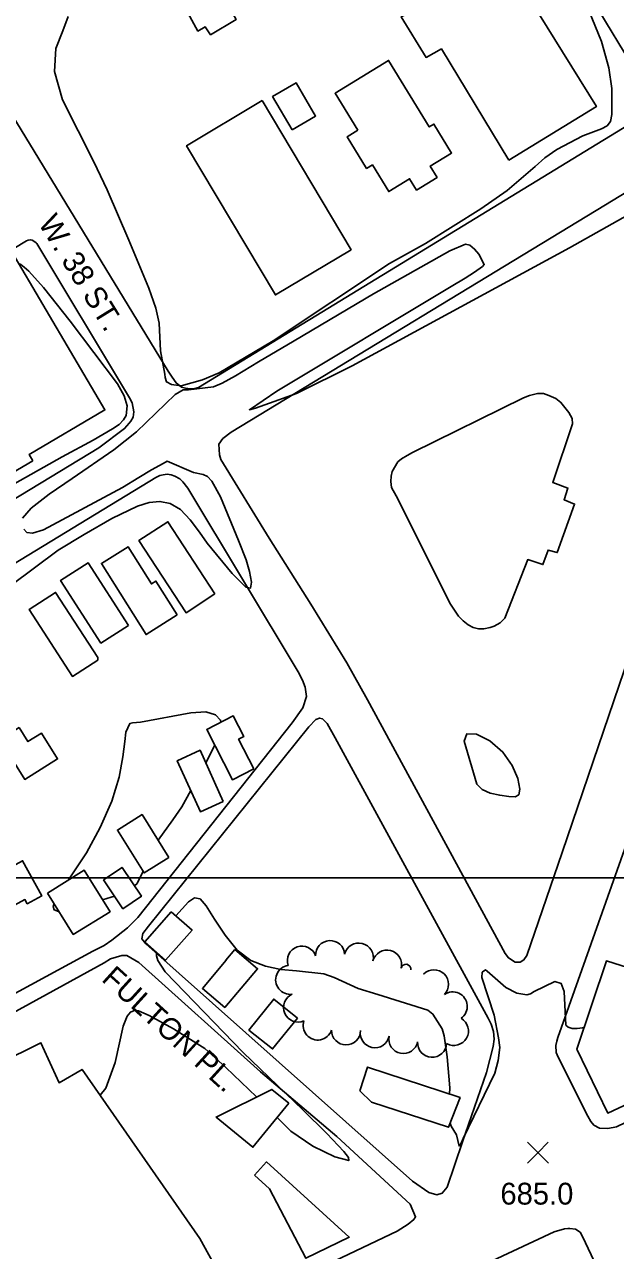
# Model space of a CAD drawing. Extents: x 79600 to 91800, y 75600 to 84400.
# Drawn here: x 81024 to 81430, y 82744 to 83587 of the extents above; entities that cross this region are included whole.
import ezdxf

# ---------------------------------------------------------------- set-up
doc = ezdxf.new("R2010")
doc.units = 0
for name, color, linetype in [('084-085$0$BLDG', 7, 'Continuous'), ('084-085$0$GRID', 7, 'Continuous'), ('084-085$0$INTER', 7, 'Continuous'), ('084-085$0$ROAD', 7, 'Continuous'), ('084-085$0$ROAD-NAME', 7, 'Continuous'), ('084-085$0$SPOTMARK', 7, 'Continuous'), ('084-085$0$SPOTS', 7, 'Continuous'), ('084-085$0$TREES', 7, 'Continuous')]:
    doc.layers.add(name, color=color, linetype=linetype)

# ---------------------------------------------------------------- blocks, each defined once
blk = doc.blocks.new('084-085$0$SPOTX')
at = {"layer": '084-085$0$SPOTMARK'}
for p, q in [((-0.37, 0.358), (0.351, -0.358)), ((-0.012, 0), (-0.37, -0.358)), ((-0.012, 0), (0.347, 0.358))]:
    blk.add_line(p, q, dxfattribs=at)

msp = doc.modelspace()

# ---------------------------------------------------------------- linework, layer by layer
at = {"layer": '084-085$0$BLDG'}
for points in [[(81106.06, 83643.89), (81126.19, 83656.27), (81134.29, 83642.84), (81138.56, 83645.29), (81167.76, 83598.92), (81165.47, 83597.55), (81169.6, 83590.22), (81151.9, 83579.68), (81148.24, 83585.02), (81143.2, 83582.26), (81127.91, 83610.18), (81115.1, 83602.08), (81103.33, 83624.65), (81114.16, 83630.31)], [(81357.1, 83493.34), (81310.63, 83569.91), (81300.11, 83564.1), (81282.99, 83592.01), (81292.9, 83597.06), (81280.98, 83618.41), (81295.78, 83625.45), (81295.16, 83627.43), (81294.7, 83631.09), (81294.55, 83634.75), (81295.15, 83638.72), (81296.98, 83642.85), (81299.12, 83645.44), (81302.78, 83648.19), (81305.52, 83649.72), (81307.66, 83650.33), (81311.17, 83650.64), (81314.68, 83650.65), (81316.2, 83650.65), (81317.88, 83650.65), (81326.89, 83646.08), (81329.03, 83642.57), (81343.06, 83649.91), (81417.2, 83530.33)], [(81253.1, 83514.02), (81245.85, 83509.57), (81259.23, 83487.73), (81263.23, 83490.18), (81274.44, 83471.89), (81288.79, 83480.68), (81293.54, 83472.93), (81307.73, 83481.63), (81302.98, 83489.38), (81317.66, 83498.38), (81305.49, 83518.23), (81302.33, 83516.29), (81274.32, 83562), (81237.52, 83539.44)], [(81208.07, 83514.24), (81224.16, 83523.72), (81210.67, 83546.63), (81194.58, 83537.15)], [(81187.46, 83534.45), (81248.55, 83431.89), (81196.45, 83400.86), (81135.36, 83503.42)], [(81029.59, 83286.81), (81027.11, 83291.02), (81079.2, 83321.69), (81015.17, 83430.43), (80919.56, 83374.13), (80927.91, 83359.94), (80918.99, 83354.69), (80977.15, 83255.93)], [(81400.77, 83312.07), (81387.22, 83271.92), (81397.61, 83267.96), (81395.02, 83260.03), (81402.2, 83256.98), (81390.32, 83223.7), (81384.06, 83225.37), (81380.41, 83215.45), (81370.03, 83218.8), (81354.35, 83178.64), (81351.15, 83175.28), (81347.03, 83172.99), (81344.28, 83172.07), (81339.86, 83171.3), (81336.19, 83171.3), (81332.38, 83172.21), (81329.02, 83173.89), (81325.51, 83176.63), (81322.45, 83179.99), (81316.95, 83188.07), (81279.49, 83262.66), (81276.28, 83268.31), (81275.97, 83272.43), (81276.12, 83276.09), (81276.88, 83279.45), (81280.69, 83286.01), (81283.28, 83288.15), (81287.09, 83290.45), (81290.75, 83292.43), (81367.18, 83330.05), (81371.3, 83331.58), (81376.64, 83332.96), (81380.91, 83332.96), (81384.57, 83331.75), (81389.31, 83329.61), (81392.82, 83326.87), (81398.17, 83320.01), (81400.46, 83315.89)], [(81154.93, 83195.25), (81122.55, 83244.87), (81102.65, 83231.88), (81135.02, 83182.26)], [(81128.96, 83180.75), (81114.28, 83204.06), (81111.26, 83202.16), (81095.17, 83227.71), (81076.87, 83216.19), (81107.62, 83167.32)], [(81095.38, 83173.58), (81067.64, 83216.62), (81048.77, 83204.46), (81076.51, 83161.42)], [(81074.33, 83149.7), (81074.33, 83151.58), (81045.38, 83196.3), (81027.13, 83184.49), (81056.94, 83138.45)], [(81181.55, 83074.93), (81171.14, 83095.35), (81174.69, 83097.16), (81167.45, 83111.35), (81149.32, 83102.11), (81166.98, 83067.49)], [(81020.31, 83103.28), (81026.31, 83093.73), (81035.61, 83099.57), (81046.73, 83081.84), (81024.15, 83067.67), (81007.03, 83094.94)], [(81160.64, 83052.57), (81144.75, 83087.69), (81129.04, 83080.58), (81144.92, 83045.46)], [(81123.24, 83014.03), (81104.76, 83043.51), (81087.84, 83032.9), (81106.32, 83003.42)], [(81003.87, 82993.5), (80994.52, 82988.42), (81002.68, 82973.42), (81024.21, 82985.12), (81025.82, 82982.16), (81035.78, 82987.57), (81022.65, 83011.73), (81000.51, 82999.69)], [(81039.8, 82989.58), (81065.04, 83005.26), (81082.76, 82976.76), (81057.52, 82961.07)], [(81078.29, 82998.59), (81091.59, 82978.76), (81104.38, 82987.34), (81091.09, 83007.17)], [(81124.9, 82976.66), (81106.64, 82955.92), (81120.95, 82943.32), (81139.21, 82964.06)], [(81168.56, 82950.76), (81162.41, 82943.51), (81162.65, 82943.31), (81146.27, 82923.97), (81161.69, 82910.91), (81184.21, 82937.51)], [(81494.44, 82870.8), (81425.03, 82838.22), (81403.77, 82882.16), (81424.17, 82942.92), (81468.28, 82928.92), (81471.8, 82918.7), (81453.04, 82909.83), (81448.63, 82894.87), (81450.77, 82889.83), (81466.79, 82895.95), (81465.41, 82900.83), (81478.07, 82906.34), (81480.82, 82902.38), (81502.03, 82911.71), (81508.45, 82899.65), (81506.01, 82898.28), (81515.8, 82875.4), (81498.26, 82866.22)], [(81211.58, 82903.6), (81195.32, 82916.61), (81178.3, 82895.35), (81194.56, 82882.34)], [(81254.54, 82853.63), (81259.87, 82869.96), (81323.53, 82848.96), (81315.61, 82828.5), (81262.64, 82845.85)], [(81205.74, 82845.04), (81181.08, 82814.8), (81155.66, 82835.53), (81194.02, 82854.6)], [(81182.02, 82795.57), (81192.46, 82786.11), (81217.41, 82738.52), (81247.31, 82753.05), (81190.26, 82804.68)]]:
    msp.add_lwpolyline(points, close=True, dxfattribs=at)
msp.add_lwpolyline([(81165.55, 82713.75), (81144.6, 82752.03), (81063.6, 82868.25), (81047.74, 82859.08), (81035.2, 82886.69), (80947.64, 82843.26), (80969.06, 82792.01), (80928.17, 82771.36), (80965.79, 82690.97)], dxfattribs=at)
at = {"layer": '084-085$0$GRID'}
msp.add_line((85000, 83000), (80000, 83000), dxfattribs=at)
at = {"layer": '084-085$0$INTER'}
msp.add_line((81148.61, 83079.17), (81154.84, 83091.29), dxfattribs=at)
for points in [[(81053.97, 83592.15), (81050.21, 83582.46), (81045.54, 83570.17), (81044.48, 83554.44), (81050.19, 83534.94), (81071.59, 83492.22), (81080.86, 83473.01), (81095.6, 83438.37), (81109.41, 83405.4), (81114.2, 83391.79), (81116.45, 83381.49), (81117.54, 83362.44), (81120.36, 83346.39), (81120.66, 83343.95), (81121.65, 83341.04), (81125.15, 83339.11), (81131.62, 83338.34), (81146.45, 83342.34), (81157.79, 83347.34), (81194.89, 83369.18), (81274.84, 83422.48), (81299.71, 83436.22), (81337.81, 83460.07), (81355.79, 83472.5), (81375.16, 83489.05), (81381.75, 83495), (81389.91, 83500.75), (81407.85, 83510.25), (81420.71, 83514.99), (81424.59, 83517.03), (81426.86, 83520.02), (81427.9, 83524.76), (81427.82, 83542.65), (81425.79, 83556.86), (81420.73, 83574.94), (81412, 83596.36)], [(81483.02, 83480.58), (81398.8, 83433.14), (81249.29, 83352.05), (81211.03, 83332.95), (81189.13, 83325.32), (81182.74, 83323.03), (81178.65, 83321.82), (81197.4, 83334.53), (81317.45, 83406.69), (81326.92, 83412.39), (81333.38, 83416.45), (81338.96, 83420.38), (81340.11, 83421.77), (81336.35, 83428.75), (81333.46, 83432.34), (81330.3, 83434.94), (81327.13, 83435.66), (81316.55, 83431.11), (81263.87, 83401.63), (81209.29, 83369.31), (81184.9, 83354.73), (81168.98, 83345.25), (81159.77, 83340.08), (81153.92, 83337.59), (81136.7, 83335.57), (81133.07, 83335.61), (81127.55, 83332.26), (81100.91, 83306.59), (81085.46, 83294.2), (81056.71, 83274.69), (81040.99, 83263.92), (81028.49, 83254.18), (81022.62, 83247.27)], [(80808.27, 83155.56), (80849.24, 83176.84), (80887.42, 83192.72), (80893.53, 83195.29), (80897.22, 83197.43), (80899.48, 83201.37), (80900.42, 83203.87), (80903.71, 83207.28), (81049.81, 83289.38), (81071.25, 83301.03), (81084.57, 83308.63), (81089.04, 83311.79), (81092.11, 83314.85), (81093.86, 83317.97), (81094.45, 83324.46), (81092.59, 83331.37), (81087.82, 83339.78), (81055.39, 83382.84), (81036.97, 83405.92), (81026.91, 83417.03), (81023.79, 83419.95), (81021.4, 83421.74), (81019.87, 83422.44)], [(81023.54, 83239.69), (81025.66, 83237.45), (81029.48, 83236.91), (81037, 83239.31), (81091.31, 83268.35), (81102.48, 83275.29), (81111.29, 83280.61), (81119.31, 83284.97), (81122.16, 83286.44), (81140.07, 83278.65), (81146.86, 83277.37), (81149.77, 83275.89), (81152.7, 83272.85), (81158.74, 83261.93), (81171.06, 83231.9), (81176.3, 83218.76), (81178.71, 83210.69), (81180.11, 83203.34), (81179.48, 83199.2), (81176.21, 83199.93), (81166.73, 83209.17), (81149.65, 83230.18), (81144.32, 83237.74), (81137.99, 83246.16), (81131.17, 83253.31), (81124.23, 83257.49), (81117.1, 83258.86), (81109.6, 83258.04), (81101.59, 83255.59), (81084.03, 83247.18), (81065.02, 83236.16), (81047.04, 83225.31), (81014.57, 83201.13)], [(81159.02, 83107.05), (81158.78, 83108.48), (81155.4, 83112.2), (81148.65, 83114.07), (81138.34, 83113.53), (81103.81, 83107.1), (81098.31, 83106.56), (81096.42, 83106.16), (81093.57, 83100.19), (81092.87, 83093.65)], [(81092.87, 83093.65), (81091.65, 83083.2), (81089.02, 83069.31), (81083.94, 83052.75), (81075.93, 83034.64), (81066.65, 83017.31), (81054.27, 82998.57)], [(81115.76, 83025.96), (81125.9, 83039.87), (81132.19, 83048.86), (81138.32, 83060.04)], [(81099.63, 82994.43), (81101.51, 82996.22), (81105.53, 83004.69)], [(81077.64, 82985), (81083.54, 82986.69), (81085.76, 82987.44)], [(81316.3, 82851.35), (81316.35, 82855.55), (81314.57, 82876.9), (81312.51, 82891.28), (81311.27, 82896.14), (81304.85, 82906.33), (81301.37, 82909.05), (81266.87, 82919.85), (81253.46, 82923.94), (81236.79, 82931.46), (81229.82, 82934.01), (81211.02, 82936.09), (81200.31, 82937.09), (81189.71, 82939.19), (81179.59, 82943.3), (81170.22, 82950.31), (81161.85, 82960.49), (81154.7, 82971.59), (81148.98, 82980.7), (81144.67, 82985.54), (81140.93, 82986.24), (81136.73, 82983.5), (81127.96, 82973.96)], [(81044.26, 82982.41), (81043.63, 82980.26), (81044.41, 82977.91), (81047.34, 82976.96), (81047.62, 82977)], [(81114.67, 82948.84), (81114.68, 82946.42), (81115.55, 82943.11), (81120.63, 82935.3), (81174.22, 82880), (81215.39, 82840.41), (81231.82, 82824.15), (81243.53, 82811.82), (81246.74, 82807.7), (81246.92, 82805.64), (81237.4, 82808.17), (81222.24, 82815.43), (81207.1, 82825.73), (81197.73, 82835.2)], [(81408.85, 82897.28), (81407.65, 82896.9), (81403.91, 82896.37), (81400.55, 82896.53), (81397.89, 82897.3), (81396.16, 82898.74), (81395.05, 82921.82), (81393.05, 82927.34), (81388.7, 82928.66), (81374.46, 82921.79), (81371.91, 82920.3), (81369.4, 82919.66), (81362.46, 82920.84), (81354.84, 82924.61), (81342.09, 82935.95), (81340.88, 82936.68), (81338.73, 82935.05), (81338.41, 82931.57), (81346.88, 82905.57), (81349.87, 82890.02), (81350.88, 82883.4), (81349.71, 82874.53), (81347.32, 82865.76), (81325.69, 82820.81), (81324.01, 82817.24), (81322.77, 82815.55), (81321.07, 82823.33), (81317.47, 82829.22), (81316.72, 82831.36)], [(81183.54, 82849.39), (81162.42, 82869.59), (81147.92, 82882.64), (81126.31, 82896.12), (81109.59, 82905.29), (81102.24, 82908.67), (81100.01, 82908.96), (81096.76, 82907.68), (81094.54, 82904.9), (81091.71, 82897.93), (81086.35, 82873.13), (81079.9, 82855.41), (81075.96, 82850.53)]]:
    msp.add_lwpolyline(points, dxfattribs=at)
msp.add_lwpolyline([(81338.58, 83060.83), (81344.18, 83058.34), (81350.79, 83056.76), (81356.96, 83055.88), (81361.44, 83055.73), (81364, 83057.12), (81364.6, 83061.09), (81363.18, 83068.22), (81359.42, 83077.24), (81352.95, 83086.45), (81343.94, 83094.17), (81334.73, 83098.87), (81328.2, 83099.03), (81326.38, 83093.88), (81335.01, 83064.45)], close=True, dxfattribs=at)
at = {"layer": '084-085$0$ROAD'}
for points in [[(81447.57, 83522.73), (81143.59, 83337.16), (81140.99, 83336.4), (81137.79, 83336.24), (81134.74, 83336.7), (81131.99, 83337.46), (81128.17, 83340.35), (81125.57, 83344.17), (81122.82, 83348.28), (80975.47, 83589.89), (80973.63, 83594.16), (80973.17, 83597.36), (80975, 83600.88), (80978.51, 83603.78), (81282.19, 83788.89), (81286.61, 83792.4), (81290.43, 83793.01), (81293.33, 83792.41), (81296.84, 83790.73), (81300.2, 83788.29), (81305.4, 83782.19), (81316.71, 83762.97), (81405.82, 83618.07), (81454.12, 83538.15)], [(81532.22, 83423.76), (81393.72, 83017.37), (81369.37, 82946.53), (81367.39, 82943.63), (81364.8, 82941.95), (81361.29, 82941.94), (81356.71, 82944.99), (81354.57, 82947.89), (81259.93, 83122.39), (81245.71, 83147.86), (81233.33, 83168), (81220.8, 83188.28), (81192.22, 83233.58), (81159.05, 83287.58), (81158.13, 83290.78), (81157.67, 83298.26), (81160.26, 83302.08), (81166.05, 83306.51), (81423.52, 83462.73), (81554.23, 83542.36)], [(81032.54, 83436.07), (81092.77, 83335.74), (81096.13, 83329.94), (81097.97, 83326.59), (81099.19, 83320.49), (81098.59, 83316.82), (81097.06, 83313.92), (81095.84, 83312.55), (81092.79, 83308.88), (81075.1, 83295.74), (80526.76, 82963.13), (80517.46, 82958.54), (80514.86, 82958.38), (80512.73, 82958.84), (80508.3, 82961.28), (80504.33, 82964.94), (80498.52, 82972.26), (80437.27, 83071.46)], [(81016.67, 83432.73), (81025.34, 83437.93), (81026.4, 83438.47), (81027.87, 83438.73), (81029.2, 83438.47), (81030.4, 83437.8), (81031.87, 83436.6), (81032.54, 83436.07)], [(80948.7, 83174.59), (81114.34, 83275.33), (81116.94, 83276.55), (81119.38, 83277.16), (81122.13, 83277.47), (81124.72, 83277.17), (81127.32, 83276.25), (81130.83, 83274.27), (81132.81, 83272.29), (81136.18, 83268.02), (81212.15, 83141.57), (81215.05, 83135.93), (81216.89, 83131.05), (81217.81, 83124.79), (81215.37, 83117.01), (81207.91, 83106.62), (81101.96, 82972.83), (81094.8, 82965.65), (81083.97, 82957.25), (81078.63, 82953.58), (81070.85, 82949.6), (80665.1, 82729.3)], [(81647.27, 83269.35), (81509.1, 83184.13), (81505.89, 83182.14), (81500.55, 83178.32), (81495.98, 83173.74), (81493.08, 83170.84), (81490.34, 83167.63), (81488.66, 83164.73), (81486.84, 83161.22), (81421.23, 82976.18), (81390.64, 82890.23), (81390.03, 82887.64), (81389.42, 82884.74), (81389.58, 82880.01), (81390.96, 82876.8), (81411.45, 82836.07), (81413.43, 82832.41), (81415.57, 82829.97), (81419.39, 82827.84), (81425.04, 82827.69), (81430.99, 82828.92), (81656.13, 82937.46)], [(80666.18, 82718.61), (80921.84, 82855.75), (81078.64, 82941.67), (81083.07, 82944.42), (81091, 82946.72), (81094.36, 82946.57), (81102.6, 82941.7), (81186.16, 82866.54), (81238.7, 82822.17), (81289.26, 82775.67), (81292.93, 82766.98), (81291.71, 82765.15), (81287.75, 82761.79), (81280.12, 82757.2), (81070.37, 82657.19)], [(81519.21, 82517.02), (81407.56, 82753.35), (81406.18, 82756.4), (81402.97, 82758.54), (81399.01, 82758.84), (81397.63, 82758.84), (81395.19, 82758.68), (81388.17, 82756.69), (81214.12, 82675.18)]]:
    msp.add_lwpolyline(points, dxfattribs=at)
msp.add_lwpolyline([(81325.24, 82818.44), (81314.58, 82787.3), (81311.23, 82783.33), (81307.41, 82782.1), (81302.07, 82783.62), (81290.77, 82791.4), (81107.32, 82954.67), (81104.57, 82958.18), (81105.33, 82961.69), (81109.14, 82966.73), (81219.51, 83103.73), (81224.23, 83108.93), (81226.83, 83109.84), (81228.81, 83109.39), (81232.17, 83106.19), (81237.68, 83096.27), (81339.95, 82908.65), (81342.71, 82903.62), (81344.85, 82899.35), (81346.53, 82894.46), (81346.84, 82889.12), (81346.23, 82884.09), (81341.67, 82866.07)], close=True, dxfattribs=at)
at = {"layer": '084-085$0$TREES'}
for centre, radius, start, end in [((81214.69, 82943.06), 10, 18.90338, 198.90338), ((81234.13, 82946.89), 10, 3.43754, 183.43754), ((81253.84, 82945.17), 10, 346.57688, 166.57688), ((81273.25, 82940.35), 10, 345.50373, 165.50373), ((81206.67, 82929.92), 10, 98.31472, 278.31472), ((81286.24, 82937.26), 3.36, 349.9051, 169.9051), ((81305.55, 82926.78), 10, 315.48712, 135.48712), ((81212.13, 82910.87), 10, 113.67129, 293.67129), ((81318.45, 82911.6), 10, 305.21983, 125.21983), ((81225.61, 82898.48), 10, 161.13706, 341.13706), ((81319.24, 82894.76), 10, 240.1562, 60.1562), ((81245.07, 82895.18), 10, 179.64236, 359.64236), ((81264.88, 82893.16), 10, 168.68625, 348.68625), ((81284.49, 82889.23), 10, 168.68625, 348.68625), ((81304.28, 82886.68), 10, 176.60389, 356.60389)]:
    msp.add_arc(centre, radius, start, end, dxfattribs=at)

# ---------------------------------------------------------------- block references
at = {"layer": '084-085$0$SPOTS', "xscale": 20, "yscale": 20}
msp.add_blockref('084-085$0$SPOTX', (81377.22, 82811.01), dxfattribs=at)

# ---------------------------------------------------------------- texts
at = {"layer": '084-085$0$ROAD-NAME'}
for s, rotation, p in [('W. 38 ST.', 301.75227, (81032.97, 83450.18)), ('FULTON PL.', 317.74559, (81076.25, 82929.57))]:
    msp.add_text(s, height=15, rotation=rotation, dxfattribs=at).set_placement(p)
at = {"layer": '084-085$0$SPOTS'}
msp.add_text('685.0', height=15, dxfattribs=at).set_placement((81351.2, 82775.37))

doc.saveas('drawing.dxf')
